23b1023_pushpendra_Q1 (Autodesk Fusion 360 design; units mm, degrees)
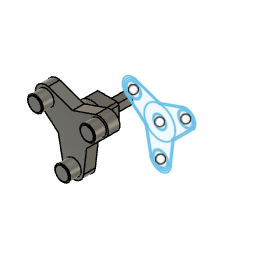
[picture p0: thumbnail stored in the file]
sketch "Sketch1" plane through (0, 0, 0) normal (0, 1, 0) x axis (1, 0, 0)
  line L1 (0, -50) -> (-50, -50)
  line L2 (5, 5) -> (5, -45)
  line L3 (-55, 5) -> (-55, -45)
  line L4 (0, 10) -> (-50, 10)
  line L5 (0, -50) -> (5, -45)
  line L6 (-50, -50) -> (-55, -45)
  line L7 (-50, 10) -> (-55, 5)
  line L8 (0, 10) -> (5, 5)
  circle C1 centre (-25, -20) radius 20
  horizontal L1
  vertical L2
  vertical L3
  horizontal L4
  dimension "d1" diameter C1 = 40
extrude "Extrude1" new body sketch "Sketch1" along normal blind 40
sketch "Sketch2" plane through (0, 0, 0) normal (0, 1, 0) x axis (1, 0, 0)
  line L1 (209.8598, -160.8894) -> (149.9827, -140.0497)
  line L2 (237.3521, -131.5387) -> (182.927, -77.3623)
  line L3 (182.927, -77.3623) -> (237.3521, -131.5387)
  line L4 (90.1092, -160.8998) -> (149.9827, -140.0497)
  line L5 (64.2251, -122.5003) -> (64.226, -122.4993)
  line L6 (64.2251, -122.5003) -> (117.0395, -77.3626)
  line L7 (175.4441, -13.9623) -> (182.927, -77.3623)
  line L8 (129.4565, -13.9626) -> (117.0395, -77.3626)
  line L9 (149.9827, -143.0497) -> (149.9827, -140.0497)
  line L10 (149.9827, -143.0497) -> (209.8598, -163.8894)
  line L11 (149.9827, -143.0497) -> (87.2122, -164.9087)
  line L12 (186.0564, -76.0072) -> (239.2002, -128.9081)
  line L13 (178.7616, -14.2007) -> (186.0564, -76.0072)
  line L14 (113.3433, -75.4777) -> (126.1146, -10.2685)
  line L15 (63.4425, -118.1253) -> (113.3433, -75.4777)
  circle C1 centre (149.9833, -100.0497) radius 40
  circle C2 centre (149.9833, -100.0497) radius 15
  circle C3 centre (149.9833, -100.0497) radius 17
  arc A1 centre (82.2338, -138.2848) radius 23.9471 clockwise from (90.1092, -160.8998) to (64.226, -122.4993)
  arc A2 centre (152.4503, -18.466) radius 23.4307 clockwise from (129.4565, -13.9626) to (175.4441, -13.9623)
  arc A3 centre (217.0912, -140.1119) radius 22 clockwise from (237.3521, -131.5387) to (209.8598, -160.8894)
  arc A4 centre (217.8866, -140.8266) radius 24.4197 clockwise from (239.2002, -128.9081) to (209.8598, -163.8894)
  arc A5 centre (152.0559, -17.3527) radius 26.8911 clockwise from (126.1146, -10.2685) to (178.7616, -14.2007)
  arc A6 centre (80.9797, -138.6451) radius 26.9929 clockwise from (87.2122, -164.9087) to (63.4425, -118.1253)
  circle C4 centre (152.4503, -18.466) radius 20
  circle C5 centre (152.4503, -18.466) radius 17
  circle C6 centre (217.0912, -140.1119) radius 20
  circle C7 centre (217.0912, -140.1119) radius 17
  circle C8 centre (82.2338, -138.2848) radius 20
  circle C9 centre (82.2338, -138.2848) radius 17
  point P5 (149.9827, -140.0497)
  point P8 (182.927, -77.3623)
  point P10 (117.0395, -77.3626)
  point P6 (209.8598, -160.8894)
  point P9 (90.1092, -160.8998)
  point P14 (175.4441, -13.9623)
  point P15 (129.4565, -13.9626)
  point P18 (149.9827, -143.0497)
  point P19 (209.8598, -163.8894)
  concentric C1 C2
  concentric C2 C3
  coincident C1 P5
  coincident C1 P8
  coincident C1 P10
  tangent L4 A1
  tangent L8 A2
  tangent L1 A3
  vertical L9
  parallel L1 L10
  parallel L4 L11
  tangent L10 A4
  parallel L7 L13
  tangent L13 A5
  tangent L15 A6
  parallel L3 L12
  parallel L8 L14
  parallel L6 L15
  concentric A2 C4
  concentric A2 C5
  concentric A3 C6
  concentric A3 C7
  concentric A1 C8
  concentric C8 C9
  dimension "d4" diameter C1 = 80
  dimension "d5" diameter C2 = 30
  dimension "d6" diameter C3 = 34
  dimension "d8" distance P5 P6 = 63.4
  dimension "d11" angle L1 L4 = 141.61
  dimension "d12" distance P5 P9 = 63.4
  dimension "d13" angle L3 L7 = 141.6
  dimension "d14" distance P8 P14 = 63.4
  dimension "d16" distance P10 P15 = 63.4
  dimension "d17" distance P5 P18 = 3
  dimension "d18" distance P18 P19 = 63.4
  dimension "d26" diameter C4 = 40
  dimension "d27" diameter C5 = 34
  dimension "d28" diameter C6 = 40
  dimension "d29" diameter C7 = 34
  dimension "d30" diameter C8 = 40
  dimension "d31" diameter C9 = 34
extrude "Extrude2" new body sketch "Sketch2" profile of C5 C7 C9 against normal blind 30
extrude "Extrude3" add sketch "Sketch2" profile of C1 C3 L1 L3 L4 A1 L5 L6 L7 L8 A2 A3 L9 L10 L11 A4 L12 L13 A5 L14 L15 A6 C4 C5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 along normal blind 30
extrude "Extrude4" cut of existing geometry blind -30
extrude "Extrude5" add sketch "Sketch2" profile of C9 along normal blind 30
extrude "Extrude6" add sketch "Sketch2" profile of C9 against normal blind 30
extrude "Extrude7" add sketch "Sketch2" profile of C4 C5 C6 C7 C8 C9 along normal blind 30
extrude "Extrude8" add sketch "Sketch2" profile of C4 C5 C6 C7 C8 C9 against normal blind 28
extrude "Extrude9" add sketch "Sketch2" profile of C1 C3 along normal blind 50
extrude "Extrude10" new body sketch "Sketch2" profile of C2 along normal blind 105
extrude "Extrude11" add sketch "Sketch2" profile of C2 C3 along normal blind 103
sketch "Sketch3" plane through (0, 0, 0) normal (0, 1, 0) x axis (1, 0, 0)
  line L1 (160, -110) -> (160, -90)
  line L2 (140, -110) -> (160, -110)
  line L3 (140, -90) -> (140, -110)
  line L4 (160, -90) -> (140, -90)
  vertical L1
  perpendicular L1 L2
  perpendicular L2 L3
  perpendicular L1 L4
extrude "Extrude12" add sketch "Sketch3" along normal blind 145
move_face "MoveFace1"
component_from_bodies "Body->Comp1"
component_from_bodies "Body->Comp2"
joint "Assemble1" alignAngle 0 alignOffsetX 0 alignOffsetY 0 alignOffsetZ 0
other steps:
base_feature "Base Feature1"
base_feature "Base Feature1"
create_component "CreateComponent1"
remove_body "RemoveBody1"
create_component "CreateComponent2"
remove_body "RemoveBody2"
joint_origin "JointOrigin1"
joint_origin "JointOrigin1"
